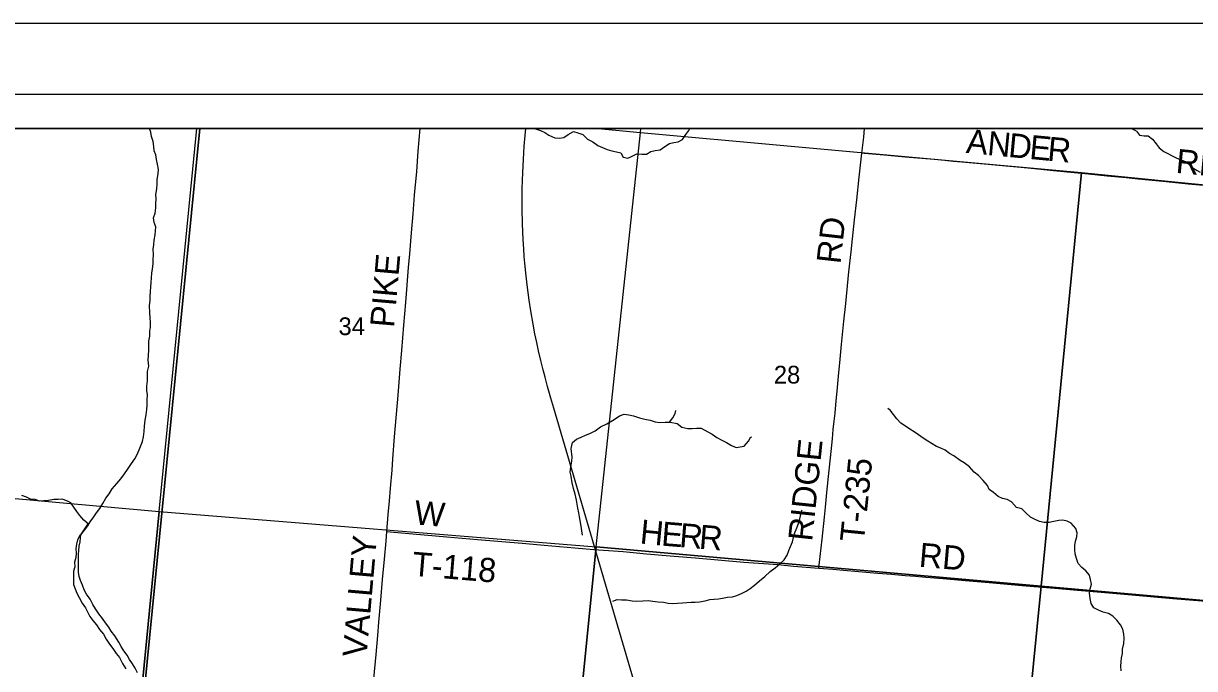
# Model space of a CAD drawing. Extents: x 0 to 1067, y 0 to 440.
# Drawn here: x 227.4 to 393.3, y 348.7 to 440 of the extents above; entities that cross this region are included whole.
import ezdxf

# ---------------------------------------------------------------- set-up
doc = ezdxf.new("R2010")
doc.units = 0
for name, color, linetype in [('GM_X_County_Road', 7, 'Continuous'), ('GM_X_County_Road_Text', 7, 'Continuous'), ('GM_X_Major_River', 7, 'Continuous'), ('GM_X_Minor_River', 7, 'Continuous'), ('GM_X_Rail_Line', 7, 'Continuous'), ('GM_X_Section', 7, 'Continuous'), ('GM_X_Section_Text', 7, 'Continuous'), ('GM_X_Township_Road', 7, 'Continuous'), ('GM_X_Township_Road_Text', 7, 'Continuous'), ('GM_X_US_Shield', 7, 'Continuous'), ('SH_Border', 7, 'Continuous'), ('SH_Cut_Line', 7, 'Continuous'), ('SH_Text', 7, 'Continuous')]:
    doc.layers.add(name, color=color, linetype=linetype)

msp = doc.modelspace()

# ---------------------------------------------------------------- linework, layer by layer
at = {"layer": 'GM_X_County_Road'}
for points in [[(278.87, 368.07), (279.08, 370.51), (279.24, 372.44), (279.39, 374.22), (279.61, 376.78), (279.74, 378.38), (279.98, 381.47), (280.46, 387.39), (280.77, 391.08), (281, 393.7), (281.29, 397.3), (281.55, 400.51), (281.95, 405.47), (282.12, 407.38), (282.37, 410.37), (282.59, 413.05), (282.8, 415.69), (283.11, 419.03), (283.32, 421.93), (283.6, 425.11)], [(277.05, 347.22), (277.35, 350.65), (277.59, 353.38), (277.76, 355.24), (278.03, 358.36), (278.28, 361.29), (278.53, 364.15), (278.76, 366.72), (278.87, 368.07)]]:
    msp.add_lwpolyline(points, dxfattribs=at)
at = {"layer": 'GM_X_Major_River'}
for points in [[(235.53, 367.63), (236.04, 368.27), (236.52, 368.87), (236.88, 369.47), (237.4, 370.14), (237.78, 370.74), (238.21, 371.32), (238.64, 372.04), (239.09, 372.8), (239.54, 373.4), (240, 374.14), (240.63, 374.87), (241.2, 375.54), (241.74, 376.23), (242.17, 376.86), (242.72, 377.73), (243.19, 378.35), (243.51, 378.98), (243.8, 379.63), (244.25, 380.8), (244.4, 381.48), (244.52, 382.25), (244.56, 382.98), (244.65, 383.84), (244.77, 384.61), (244.88, 385.34), (244.94, 385.97), (244.92, 386.68), (244.97, 387.45), (244.89, 388.04), (244.87, 388.66), (245, 389.43), (244.98, 390.16), (244.97, 390.75), (245.15, 391.49), (245.09, 392.34), (245.11, 393.02), (245.18, 393.75), (245.15, 394.36), (245.15, 395.04), (245.33, 395.74), (245.32, 396.43), (245.41, 397.01), (245.41, 397.67), (245.36, 398.31), (245.31, 399.02), (245.25, 400.09), (245.34, 400.79), (245.38, 401.36), (245.42, 402.06), (245.44, 402.7), (245.48, 403.31), (245.61, 404.67), (245.68, 405.28), (245.77, 405.99), (245.76, 406.55), (245.83, 407.3), (245.8, 408.03), (245.87, 408.64), (245.93, 409.34), (246.05, 410.07), (246.11, 410.64), (246.17, 411.22), (245.92, 411.8), (245.84, 412.46), (246.05, 413.16), (246.14, 413.88), (246.18, 414.47), (246.2, 415.16), (246.17, 415.79), (246.29, 416.61), (246.33, 417.24), (246.35, 417.9), (246.49, 418.71), (246.53, 419.33), (246.39, 420.06), (246.27, 420.72), (246.16, 421.41), (245.94, 421.98), (245.87, 422.57), (245.76, 423.3), (245.57, 424.01), (245.45, 424.63), (245.28, 425.11)], [(235.53, 367.63), (235.38, 367.51), (235.09, 366.9), (234.94, 366.27), (234.83, 365.66), (234.9, 365), (234.84, 364.38), (234.64, 363.75), (234.71, 363.06), (234.51, 362.46), (234.51, 361.79), (234.52, 360.56), (234.98, 359.36), (235.31, 358.74), (235.72, 357.95), (236.2, 357.28), (236.48, 356.7), (236.82, 356.07), (237.22, 355.49), (237.74, 354.88), (238.18, 354.19), (238.73, 353.53), (239.14, 352.86), (239.6, 352.14), (240.08, 351.51), (240.56, 350.83), (241.02, 350.25), (241.45, 349.42), (241.89, 348.63)], [(243.58, 348.06), (243.23, 348.73), (242.84, 349.35), (242.43, 349.96), (242.08, 350.58), (241.62, 351.19), (241.23, 351.82), (240.9, 352.4), (240.34, 353.3), (239.83, 353.96), (239.49, 354.54), (239.03, 355.17), (238.59, 355.79), (238.09, 356.45), (237.63, 357.12), (237.24, 357.75), (236.85, 358.51), (236.32, 359.23), (236.02, 359.81), (235.77, 360.5), (235.51, 361.13), (235.28, 361.73), (235.21, 362.34), (235.23, 363), (235.2, 363.6), (235.22, 364.23), (235.19, 364.81), (235.25, 365.4), (235.32, 366.03), (235.43, 366.64), (235.47, 367.21), (235.53, 367.63)]]:
    msp.add_lwpolyline(points, dxfattribs=at)
at = {"layer": 'GM_X_Minor_River'}
for points in [[(299.92, 425.11), (299.93, 425.09), (300.63, 424.84), (301.24, 424.57), (301.82, 424.19), (302.65, 423.8), (303.28, 423.74), (303.92, 423.86), (304.53, 424.29), (305.29, 424.68), (305.92, 424.5), (306.62, 424.28), (307.29, 423.64), (308.03, 423.26), (308.76, 422.74), (309.39, 422.42), (310.09, 422.15), (310.72, 421.98), (311.4, 421.84), (312.01, 421.69), (312.36, 421.09), (313.01, 420.93), (313.59, 421.21), (314.26, 421.53), (314.97, 421.51), (315.63, 421.51), (316.25, 421.88), (316.85, 422), (317.56, 422.11), (318.23, 422.57), (318.9, 423.01), (319.5, 423.15), (320.12, 423.26), (320.72, 423.59), (321.2, 424.28), (321.65, 424.85), (321.78, 425.11)], [(385.01, 424.77), (384.38, 425.1), (384.37, 425.11)], [(385.01, 424.77), (385.45, 424.18), (386.11, 424.09), (386.68, 424.08), (387.3, 423.64), (387.81, 422.96), (388.24, 422.39), (388.88, 421.86), (389.45, 421.6), (390.06, 421.26), (390.65, 420.96), (391.22, 420.72), (391.81, 420.49), (392.4, 420.14), (392.99, 419.55), (393.63, 419.2), (394.04, 418.93)], [(318.91, 383.58), (319.37, 384.18), (319.68, 384.79), (319.78, 385.22)], [(382.84, 348.37), (382.79, 349.02), (382.88, 349.63), (382.89, 350.2), (383.03, 350.81), (383.07, 351.43), (383.23, 352.24), (383.27, 352.97), (383.24, 353.54), (383.1, 354.28), (382.76, 354.86), (382.23, 355.51), (381.68, 356.1), (381.05, 356.46), (380.33, 356.66), (379.65, 356.93), (378.98, 357.27), (378.61, 357.88), (378.45, 358.61), (378.38, 359.39), (378.49, 359.98), (378.65, 360.61), (378.51, 361.3), (378.36, 361.9), (377.88, 362.5), (377.3, 362.98), (376.77, 363.56), (376.52, 364.25), (376.36, 364.9), (376.31, 365.51), (376.3, 366.08), (376.41, 366.7), (376.57, 367.31), (376.61, 367.9), (376.46, 368.49), (375.8, 369.24), (375.22, 369.56), (374.61, 369.67), (374.04, 369.64), (373.31, 369.5), (372.66, 369.38), (371.96, 369.38), (371.28, 369.49), (370.61, 369.81), (370, 370.1), (369.36, 370.73), (368.78, 371.27), (368.06, 371.5), (367.35, 372.27), (366.7, 372.63), (366.05, 372.77), (365.46, 373.04), (364.8, 373.6), (364.19, 374.01), (363.92, 374.59), (363.3, 375.31), (362.68, 375.99), (362.04, 376.49), (361.38, 377.26), (360.64, 377.78), (360.06, 378.14), (359.17, 378.8), (358.56, 379.14), (357.92, 379.59), (357.31, 379.9), (356.72, 380.13), (356.08, 380.51), (355.49, 380.85), (354.82, 381.28), (354.18, 381.75), (353.53, 382.18), (352.95, 382.56), (352.3, 383.01), (351.68, 383.42), (351.08, 384.03), (350.6, 384.65), (350.14, 385.26), (349.82, 385.5)], [(306.56, 367.55), (306.33, 369.13), (306.16, 370.14), (306.06, 370.71), (305.9, 371.37), (305.75, 372.52), (305.55, 373.39), (305.32, 374.15), (305.11, 374.95), (304.98, 375.91), (304.82, 376.48), (304.95, 377.21), (305.07, 378.02), (305.11, 378.62), (304.96, 379.85), (305.17, 380.69), (305.75, 381.15), (306.4, 381.45), (307.02, 381.7), (307.6, 381.96), (308.36, 382.32), (309.15, 382.89), (310.03, 383.34), (311.07, 383.93), (311.82, 384.45), (312.46, 384.68), (313.16, 384.62), (313.82, 384.46), (314.65, 384.19), (315.42, 383.98), (316.17, 383.82), (316.87, 383.62), (317.52, 383.49), (318.3, 383.56), (318.98, 383.58), (320, 383.39), (320.65, 382.85), (321.48, 382.67), (322.1, 382.67), (322.74, 382.72), (323.38, 382.7), (324.34, 382.17), (324.94, 381.86), (325.59, 381.38), (326.33, 381.02), (326.98, 380.68), (327.7, 380.25), (328.33, 379.96), (328.9, 380.08), (329.49, 380.15), (330.11, 380.87), (330.44, 381.47), (330.49, 381.45)], [(235.53, 367.63), (236.57, 369.18), (235.95, 369.7), (235.38, 370.34), (234.98, 370.92), (234.57, 371.52), (234.13, 372.15), (233.55, 372.44), (232.89, 372.64), (232.32, 372.59), (231.73, 372.61), (230.95, 372.45), (230.32, 372.44), (229.7, 372.39), (229.09, 372.59), (228.43, 372.66), (227.85, 372.93), (227.17, 373.2)], [(310.88, 358.21), (311.48, 358.45), (312.09, 358.41), (312.8, 358.43), (313.62, 358.29), (314.27, 358.21), (315.12, 358.27), (315.87, 358.3), (316.55, 358.21), (317.28, 358.14), (318.07, 358.09), (318.73, 357.96), (319.37, 357.87), (320.05, 357.92), (320.73, 357.99), (321.35, 358.04), (321.97, 358.07), (322.54, 358.1), (323.15, 358.13), (323.95, 358.26), (324.62, 358.47), (325.24, 358.52), (325.83, 358.57), (326.4, 358.67), (327.13, 358.78), (327.84, 358.85), (328.42, 359.02), (329.08, 359.32), (329.75, 359.66), (330.33, 360.01), (330.94, 360.47), (331.64, 361.11), (332.39, 361.73), (333.16, 362.41), (333.86, 362.96), (334.51, 363.49), (335.12, 364.09), (335.55, 364.74), (335.8, 365.39), (336.04, 365.98), (336.31, 366.63), (336.47, 367.22), (336.6, 367.81), (336.92, 368.59), (337.19, 369.22), (337.36, 369.86), (337.5, 370.47), (337.65, 371.06), (337.7, 371.12)]]:
    msp.add_lwpolyline(points, dxfattribs=at)
at = {"layer": 'GM_X_Rail_Line'}
msp.add_lwpolyline([(315.08, 342.78), (302.53, 385.54), (302.1, 386.94), (301.62, 388.61), (301.28, 389.91), (301, 390.99), (300.69, 392.27), (300.35, 393.67), (300.1, 394.85), (299.85, 396.07), (299.61, 397.41), (299.28, 399.31), (299.04, 400.85), (298.75, 403.01), (298.56, 404.69), (298.42, 406.05), (298.34, 407.03), (298.26, 408.1), (298.17, 409.39), (298.08, 411.68), (298.03, 413.71), (298.04, 416.64), (298.11, 418.9), (298.21, 420.74), (298.33, 422.64), (298.47, 424.13), (298.57, 425.11)], dxfattribs=at)
at = {"layer": 'GM_X_Section'}
for points in [[(377.26, 418.88), (371.52, 360.33), (308.5, 365.9), (314.78, 424.55)], [(377.26, 418.88), (439.65, 412.67), (432.58, 354.98), (371.52, 360.33)], [(185.99, 376.41), (246.65, 370.91), (240.78, 310.99), (180.98, 316.33)], [(308.5, 365.9), (302.42, 305.21), (240.78, 310.99), (246.65, 370.91)], [(308.5, 365.9), (371.52, 360.33), (365.53, 299.9), (302.42, 305.21)], [(432.58, 354.98), (426.84, 293.81), (365.53, 299.9), (371.52, 360.33)]]:
    msp.add_lwpolyline(points, close=True, dxfattribs=at)
at = {"layer": 'GM_X_Township_Road'}
for points in [[(226.04, 191.96), (227.49, 191.83), (229.79, 191.63), (230.69, 191.54), (241.1, 310.88), (247.73, 377.87), (252.4, 425.11), (131, 425.11)], [(539, 425.11), (252.4, 425.11), (247.73, 377.87), (241.1, 310.88), (230.69, 191.54)], [(346.14, 421.65), (346.4, 423.9), (346.53, 425.11)], [(340.07, 362.89), (340.11, 363.31), (340.5, 366.98), (340.83, 370.13), (340.97, 371.54), (341.19, 373.62), (341.51, 376.77), (341.69, 378.51), (341.97, 381.22), (342.09, 382.51), (342.21, 383.7), (342.34, 384.85), (342.51, 386.59), (342.64, 387.97), (342.84, 390.08), (343.08, 392.46), (343.28, 394.53), (343.6, 397.84), (343.85, 400.36), (344.31, 404.82), (344.61, 407.69), (344.83, 409.5), (345.12, 412.18), (345.42, 415.04), (345.78, 418.26), (346.14, 421.65)], [(395.56, 416.96), (392.33, 417.26), (389.22, 417.58), (385.25, 417.97), (383.58, 418.14), (380.87, 418.4), (378.24, 418.66), (375.2, 418.96), (372.82, 419.19), (370.11, 419.46), (368.11, 419.66), (367.03, 419.76), (363.51, 420.09), (361.84, 420.24), (360.28, 420.38), (359.09, 420.48), (357.9, 420.59), (356.38, 420.72), (352.26, 421.07), (349.29, 421.36), (346.52, 421.61), (346.14, 421.65)], [(278.87, 368.07), (279.33, 368.03), (287.38, 367.34), (291.69, 366.96), (298.04, 366.42), (301.16, 366.17), (305.51, 365.79), (308.18, 365.55), (312.34, 365.24), (315.65, 364.94), (319.55, 364.61), (322.59, 364.36), (329.45, 363.76), (334.27, 363.4), (336.46, 363.2), (340.07, 362.89)], [(340.07, 362.89), (342.03, 362.73), (343.55, 362.6), (345.67, 362.43), (348.42, 362.2), (350.35, 362.03), (352.28, 361.87), (353.73, 361.75), (355.22, 361.62), (357.59, 361.43), (360.79, 361.15), (364.17, 360.86), (368.85, 360.46), (373.41, 360.07), (377.23, 359.73), (382.76, 359.25), (390.19, 358.6), (394.27, 358.26), (397.88, 357.98), (400.11, 357.81), (401.81, 357.67), (402.3, 357.63)]]:
    msp.add_lwpolyline(points, dxfattribs=at)
at = {"layer": 'GM_X_US_Shield'}
for points in [[(251.95, 425.11), (190.28, 425.11), (185.99, 376.41), (246.65, 370.91)], [(314.85, 425.11), (308.82, 425.11), (314.78, 424.55)]]:
    msp.add_lwpolyline(points, close=True, dxfattribs=at)
at = {"layer": 'SH_Border'}
msp.add_lwpolyline([(30, 430), (670, 430), (670, 10), (30, 10)], close=True, dxfattribs=at)
at = {"layer": 'SH_Cut_Line'}
msp.add_lwpolyline([(0, 0), (680, 0), (680, 440), (0, 440)], close=True, dxfattribs=at)
at = {"layer": 'SH_Text'}
msp.add_lwpolyline([(131, 425.11), (539, 425.11), (539, 17.11), (131, 17.11)], close=True, dxfattribs=at)

# ---------------------------------------------------------------- texts
at = {"layer": 'GM_X_County_Road_Text'}
for s, rotation, p in [('PIKE', 85.0575, (279.89, 396.87)), ('VALLEY', 85.022, (275.99, 350.19))]:
    msp.add_text(s, height=3.409, rotation=rotation, dxfattribs=at).set_placement(p)
at = {"layer": 'GM_X_Section_Text'}
for s, p in [('34', (272.03, 395.88)), ('28', (333.68, 389.03))]:
    msp.add_text(s, height=2.511, rotation=0, dxfattribs=at).set_placement(p)
at = {"layer": 'GM_X_Township_Road_Text'}
for s, height, rotation, p in [('A', 3.41, 354.6049, (360.82, 421.68)), ('N', 3.41, 354.6008, (363.81, 421.39)), ('D', 3.41, 354.6029, (366.79, 421.11)), ('E', 3.41, 354.6007, (369.78, 420.83)), ('R', 3.41, 354.5904, (372.32, 420.59)), ('RD', 3.409, 354.5823, (390.51, 418.86)), ('RD', 3.409, 83.6073, (343.1, 405.87)), ('RIDGE', 3.409, 84.001, (339.09, 366.61)), ('T-235', 3.409, 84.123, (346.42, 366.48)), ('W', 3.41, 354.9366, (282.65, 369.11)), ('H', 3.41, 354.4032, (314.62, 366.4)), ('E', 3.41, 355.3054, (317.66, 366.1)), ('R', 3.41, 355.3308, (320.21, 365.89)), ('R', 3.41, 355.3268, (323, 365.66)), ('T-118', 3.409, 355.2365, (282.36, 361.83)), ('RD', 3.409, 355.0738, (354.14, 363.11))]:
    msp.add_text(s, height=height, rotation=rotation, dxfattribs=at).set_placement(p)

doc.saveas('drawing.dxf')
